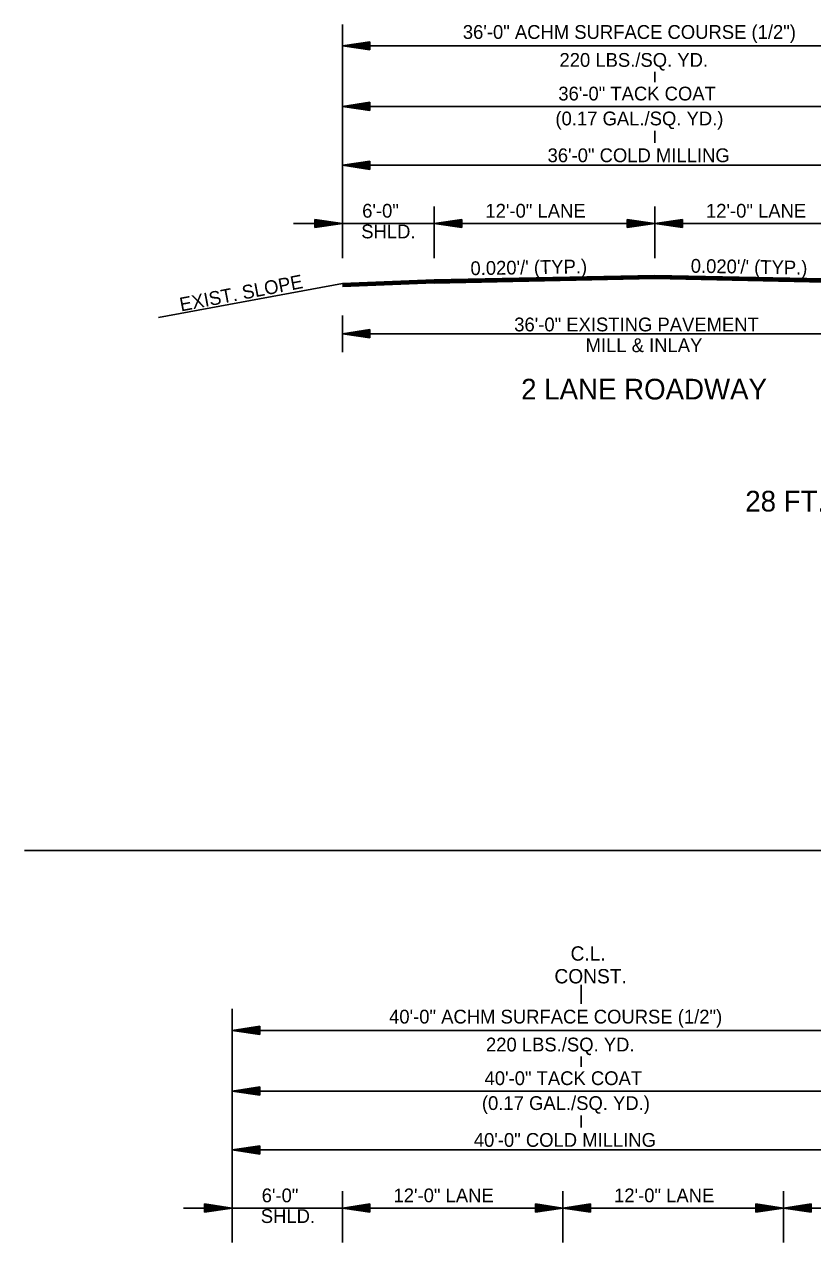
# Model space of a CAD drawing. Extents: x 549600 to 1930787, y -1955432 to 596640.
# Drawn here: x 551009 to 551438, y -1952647 to -1951984 of the extents above; entities that cross this region are included whole.
import ezdxf

# ---------------------------------------------------------------- set-up
doc = ezdxf.new("R2010")
doc.units = 0
doc.layers.add('R_Border', color=7, linetype='Continuous')
doc.layers.add('S_AREA_CALC', color=7, linetype='Continuous')

msp = doc.modelspace()

# ---------------------------------------------------------------- linework, layer by layer
at = {"layer": 'R_Border'}
msp.add_line((551008.97, -1952433.38), (552070.24, -1952433.38), dxfattribs=at)
at = {"layer": 'S_AREA_CALC'}
for p, q in [((551182.02, -1952111.3), (551182.02, -1951984.26)), ((551197.02, -1951993.68), (551182.02, -1951995.93)), ((551182.02, -1951995.93), (551522.02, -1951995.93)), ((551197.02, -1951998.18), (551182.02, -1951995.93)), ((551197.02, -1951994.06), (551184.52, -1951995.93)), ((551197.02, -1951997.81), (551184.52, -1951995.93)), ((551197.02, -1951994.44), (551187.1, -1951995.93)), ((551197.02, -1951997.43), (551187.1, -1951995.93)), ((551197.02, -1951994.82), (551189.6, -1951995.93)), ((551197.02, -1951997.05), (551189.6, -1951995.93)), ((551197.02, -1951995.2), (551192.14, -1951995.93)), ((551197.02, -1951996.66), (551192.14, -1951995.93)), ((551197.02, -1951995.58), (551194.65, -1951995.93)), ((551197.02, -1951996.29), (551194.65, -1951995.93)), ((551197.02, -1951998.18), (551197.02, -1951993.68)), ((551352.02, -1952015.68), (551352.02, -1952010.14)), ((551197.02, -1952026.65), (551182.02, -1952028.9)), ((551197.02, -1952031.15), (551182.02, -1952028.9)), ((551182.02, -1952028.9), (551522.02, -1952028.9)), ((551197.02, -1952027.02), (551184.52, -1952028.9)), ((551197.02, -1952030.77), (551184.52, -1952028.9)), ((551197.02, -1952027.41), (551187.1, -1952028.9)), ((551197.02, -1952030.39), (551187.1, -1952028.9)), ((551197.02, -1952027.78), (551189.6, -1952028.9)), ((551197.02, -1952030.02), (551189.6, -1952028.9)), ((551197.02, -1952028.16), (551192.14, -1952028.9)), ((551197.02, -1952029.63), (551192.14, -1952028.9)), ((551197.02, -1952028.55), (551194.65, -1952028.9)), ((551197.02, -1952029.25), (551194.65, -1952028.9)), ((551197.02, -1952031.15), (551197.02, -1952026.65)), ((551352.02, -1952048.64), (551352.02, -1952042.22)), ((551197.02, -1952058.62), (551182.02, -1952060.87)), ((551182.02, -1952060.87), (551522.02, -1952060.87)), ((551197.02, -1952063.12), (551182.02, -1952060.87)), ((551197.02, -1952059), (551184.52, -1952060.87)), ((551197.02, -1952062.75), (551184.52, -1952060.87)), ((551197.02, -1952059.38), (551187.1, -1952060.87)), ((551197.02, -1952062.37), (551187.1, -1952060.87)), ((551197.02, -1952059.76), (551189.6, -1952060.87)), ((551197.02, -1952061.99), (551189.6, -1952060.87)), ((551197.02, -1952060.14), (551192.14, -1952060.87)), ((551197.02, -1952061.6), (551192.14, -1952060.87)), ((551197.02, -1952060.52), (551194.65, -1952060.87)), ((551197.02, -1952061.23), (551194.65, -1952060.87)), ((551197.02, -1952063.12), (551197.02, -1952058.62)), ((551232.02, -1952111.3), (551232.02, -1952083.34)), ((551352.02, -1952111.3), (551352.02, -1952083.34)), ((551167.02, -1952090.28), (551182.02, -1952092.53)), ((551167.02, -1952090.28), (551167.02, -1952094.78)), ((551247.02, -1952090.28), (551232.02, -1952092.53)), ((551247.02, -1952090.28), (551247.02, -1952094.78)), ((551337.02, -1952090.28), (551352.02, -1952092.53)), ((551337.02, -1952090.28), (551337.02, -1952094.78)), ((551367.02, -1952090.28), (551352.02, -1952092.53)), ((551367.02, -1952090.28), (551367.02, -1952094.78)), ((551182.02, -1952092.53), (551155.5, -1952092.53)), ((551167.02, -1952090.66), (551179.51, -1952092.53)), ((551167.02, -1952091.04), (551176.93, -1952092.53)), ((551167.02, -1952091.42), (551174.44, -1952092.53)), ((551167.02, -1952091.81), (551171.89, -1952092.53)), ((551167.02, -1952092.18), (551169.39, -1952092.53)), ((551167.02, -1952094.78), (551182.02, -1952092.53)), ((551167.02, -1952093.27), (551171.89, -1952092.53)), ((551167.02, -1952094.03), (551176.93, -1952092.53)), ((551167.02, -1952094.41), (551179.51, -1952092.53)), ((551167.02, -1952093.65), (551174.44, -1952092.53)), ((551167.02, -1952092.89), (551169.39, -1952092.53)), ((551232.02, -1952092.53), (551182.02, -1952092.53)), ((551352.02, -1952092.53), (551232.02, -1952092.53)), ((551247.02, -1952094.78), (551232.02, -1952092.53)), ((551247.02, -1952090.66), (551234.52, -1952092.53)), ((551247.02, -1952094.41), (551234.52, -1952092.53)), ((551247.02, -1952091.04), (551237.1, -1952092.53)), ((551247.02, -1952094.03), (551237.1, -1952092.53)), ((551247.02, -1952091.42), (551239.6, -1952092.53)), ((551247.02, -1952093.65), (551239.6, -1952092.53)), ((551247.02, -1952091.81), (551242.14, -1952092.53)), ((551247.02, -1952093.27), (551242.14, -1952092.53)), ((551247.02, -1952092.18), (551244.65, -1952092.53)), ((551247.02, -1952092.89), (551244.65, -1952092.53)), ((551337.02, -1952090.66), (551349.51, -1952092.53)), ((551337.02, -1952091.04), (551346.93, -1952092.53)), ((551337.02, -1952091.42), (551344.44, -1952092.53)), ((551337.02, -1952091.81), (551341.89, -1952092.53)), ((551337.02, -1952092.18), (551339.39, -1952092.53)), ((551337.02, -1952094.78), (551352.02, -1952092.53)), ((551337.02, -1952093.27), (551341.89, -1952092.53)), ((551337.02, -1952094.03), (551346.93, -1952092.53)), ((551337.02, -1952094.41), (551349.51, -1952092.53)), ((551337.02, -1952093.65), (551344.44, -1952092.53)), ((551337.02, -1952092.89), (551339.39, -1952092.53)), ((551472.02, -1952092.53), (551352.02, -1952092.53)), ((551367.02, -1952094.78), (551352.02, -1952092.53)), ((551367.02, -1952090.66), (551354.52, -1952092.53)), ((551367.02, -1952094.41), (551354.52, -1952092.53)), ((551367.02, -1952091.04), (551357.1, -1952092.53)), ((551367.02, -1952094.03), (551357.1, -1952092.53)), ((551367.02, -1952091.42), (551359.6, -1952092.53)), ((551367.02, -1952093.65), (551359.6, -1952092.53)), ((551367.02, -1952091.81), (551362.14, -1952092.53)), ((551367.02, -1952093.27), (551362.14, -1952092.53)), ((551367.02, -1952092.18), (551364.65, -1952092.53)), ((551367.02, -1952092.89), (551364.65, -1952092.53)), ((551232.02, -1952123.24), (551182.02, -1952125.24)), ((551352.02, -1952120.84), (551232.02, -1952123.24)), ((551352.02, -1952121.14), (551232.02, -1952123.54)), ((551352.02, -1952121.44), (551232.02, -1952123.84)), ((551352.02, -1952121.74), (551232.02, -1952124.14)), ((551352.02, -1952122.04), (551232.02, -1952124.44)), ((551352.02, -1952122.34), (551232.02, -1952124.74)), ((551352.02, -1952122.51), (551232.02, -1952124.91)), ((551352.02, -1952120.84), (551472.02, -1952123.24)), ((551352.02, -1952121.14), (551472.02, -1952123.54)), ((551352.02, -1952121.44), (551472.02, -1952123.84)), ((551352.02, -1952121.74), (551472.02, -1952124.14)), ((551352.02, -1952122.04), (551472.02, -1952124.44)), ((551352.02, -1952122.34), (551472.02, -1952124.74)), ((551352.02, -1952122.51), (551472.02, -1952124.91)), ((551182.02, -1952125.24), (551081.95, -1952143.62)), ((551232.02, -1952123.54), (551182.02, -1952125.54)), ((551232.02, -1952123.84), (551182.02, -1952125.84)), ((551232.02, -1952124.14), (551182.02, -1952126.14)), ((551232.02, -1952124.44), (551182.02, -1952126.44)), ((551232.02, -1952124.74), (551182.02, -1952126.74)), ((551182.02, -1952142.5), (551182.02, -1952162.5)), ((551197.02, -1952150.25), (551182.02, -1952152.5)), ((551197.02, -1952154.75), (551182.02, -1952152.5)), ((551522.02, -1952152.5), (551182.02, -1952152.5)), ((551197.02, -1952150.63), (551184.52, -1952152.5)), ((551197.02, -1952154.38), (551184.52, -1952152.5)), ((551197.02, -1952151.01), (551187.1, -1952152.5)), ((551197.02, -1952153.99), (551187.1, -1952152.5)), ((551197.02, -1952151.38), (551189.6, -1952152.5)), ((551197.02, -1952153.62), (551189.6, -1952152.5)), ((551197.02, -1952151.77), (551192.14, -1952152.5)), ((551197.02, -1952153.24), (551192.14, -1952152.5)), ((551197.02, -1952152.15), (551194.65, -1952152.5)), ((551197.02, -1952152.85), (551194.65, -1952152.5)), ((551197.02, -1952150.25), (551197.02, -1952154.75)), ((551312.02, -1952516.8), (551312.02, -1952506.42)), ((551122.02, -1952646.64), (551122.02, -1952519.6)), ((551137.02, -1952529.03), (551122.02, -1952531.28)), ((551122.02, -1952531.28), (551522.02, -1952531.28)), ((551137.02, -1952533.53), (551122.02, -1952531.28)), ((551137.02, -1952529.4), (551124.52, -1952531.28)), ((551137.02, -1952533.15), (551124.52, -1952531.28)), ((551137.02, -1952529.78), (551127.1, -1952531.28)), ((551137.02, -1952532.77), (551127.1, -1952531.28)), ((551137.02, -1952530.16), (551129.6, -1952531.28)), ((551137.02, -1952532.39), (551129.6, -1952531.28)), ((551137.02, -1952530.54), (551132.14, -1952531.28)), ((551137.02, -1952532), (551132.14, -1952531.28)), ((551137.02, -1952530.92), (551134.65, -1952531.28)), ((551137.02, -1952531.63), (551134.65, -1952531.28)), ((551137.02, -1952533.53), (551137.02, -1952529.03)), ((551312.02, -1952551.02), (551312.02, -1952545.48)), ((551137.02, -1952561.99), (551122.02, -1952564.24)), ((551137.02, -1952566.49), (551122.02, -1952564.24)), ((551122.02, -1952564.24), (551522.02, -1952564.24)), ((551137.02, -1952562.37), (551124.52, -1952564.24)), ((551137.02, -1952566.12), (551124.52, -1952564.24)), ((551137.02, -1952562.75), (551127.1, -1952564.24)), ((551137.02, -1952565.73), (551127.1, -1952564.24)), ((551137.02, -1952563.12), (551129.6, -1952564.24)), ((551137.02, -1952565.36), (551129.6, -1952564.24)), ((551137.02, -1952563.51), (551132.14, -1952564.24)), ((551137.02, -1952564.97), (551132.14, -1952564.24)), ((551137.02, -1952563.89), (551134.65, -1952564.24)), ((551137.02, -1952564.59), (551134.65, -1952564.24)), ((551137.02, -1952566.49), (551137.02, -1952561.99)), ((551312.02, -1952583.98), (551312.02, -1952577.57)), ((551137.02, -1952593.97), (551122.02, -1952596.22)), ((551122.02, -1952596.22), (551522.02, -1952596.22)), ((551137.02, -1952598.47), (551122.02, -1952596.22)), ((551137.02, -1952594.34), (551124.52, -1952596.22)), ((551137.02, -1952598.09), (551124.52, -1952596.22)), ((551137.02, -1952594.72), (551127.1, -1952596.22)), ((551137.02, -1952597.71), (551127.1, -1952596.22)), ((551137.02, -1952595.1), (551129.6, -1952596.22)), ((551137.02, -1952597.33), (551129.6, -1952596.22)), ((551137.02, -1952595.48), (551132.14, -1952596.22)), ((551137.02, -1952596.94), (551132.14, -1952596.22)), ((551137.02, -1952595.86), (551134.65, -1952596.22)), ((551137.02, -1952596.57), (551134.65, -1952596.22)), ((551137.02, -1952598.47), (551137.02, -1952593.97)), ((551182.02, -1952646.64), (551182.02, -1952618.69)), ((551302.02, -1952646.64), (551302.02, -1952618.69)), ((551422.02, -1952646.64), (551422.02, -1952618.69)), ((551107.02, -1952625.63), (551122.02, -1952627.88)), ((551107.02, -1952625.63), (551107.02, -1952630.13)), ((551107.02, -1952626), (551119.51, -1952627.88)), ((551107.02, -1952626.38), (551116.93, -1952627.88)), ((551107.02, -1952626.76), (551114.44, -1952627.88)), ((551197.02, -1952625.63), (551182.02, -1952627.88)), ((551197.02, -1952626), (551184.52, -1952627.88)), ((551197.02, -1952626.38), (551187.1, -1952627.88)), ((551197.02, -1952626.76), (551189.6, -1952627.88)), ((551197.02, -1952625.63), (551197.02, -1952630.13)), ((551287.02, -1952625.63), (551302.02, -1952627.88)), ((551287.02, -1952625.63), (551287.02, -1952630.13)), ((551287.02, -1952626), (551299.51, -1952627.88)), ((551287.02, -1952626.38), (551296.93, -1952627.88)), ((551287.02, -1952626.76), (551294.44, -1952627.88)), ((551317.02, -1952625.63), (551302.02, -1952627.88)), ((551317.02, -1952626), (551304.52, -1952627.88)), ((551317.02, -1952626.38), (551307.1, -1952627.88)), ((551317.02, -1952626.76), (551309.6, -1952627.88)), ((551317.02, -1952625.63), (551317.02, -1952630.13)), ((551407.02, -1952625.63), (551422.02, -1952627.88)), ((551407.02, -1952625.63), (551407.02, -1952630.13)), ((551407.02, -1952626), (551419.51, -1952627.88)), ((551407.02, -1952626.38), (551416.93, -1952627.88)), ((551407.02, -1952626.76), (551414.44, -1952627.88)), ((551437.02, -1952625.63), (551422.02, -1952627.88)), ((551437.02, -1952626), (551424.52, -1952627.88)), ((551437.02, -1952626.38), (551427.1, -1952627.88)), ((551437.02, -1952626.76), (551429.6, -1952627.88)), ((551437.02, -1952625.63), (551437.02, -1952630.13)), ((551122.02, -1952627.88), (551095.5, -1952627.88)), ((551107.02, -1952627.15), (551111.89, -1952627.88)), ((551107.02, -1952627.52), (551109.39, -1952627.88)), ((551107.02, -1952630.13), (551122.02, -1952627.88)), ((551107.02, -1952628.61), (551111.89, -1952627.88)), ((551107.02, -1952629.37), (551116.93, -1952627.88)), ((551107.02, -1952629.75), (551119.51, -1952627.88)), ((551107.02, -1952628.99), (551114.44, -1952627.88)), ((551107.02, -1952628.23), (551109.39, -1952627.88)), ((551182.02, -1952627.88), (551122.02, -1952627.88)), ((551302.02, -1952627.88), (551182.02, -1952627.88)), ((551197.02, -1952630.13), (551182.02, -1952627.88)), ((551197.02, -1952629.75), (551184.52, -1952627.88)), ((551197.02, -1952629.37), (551187.1, -1952627.88)), ((551197.02, -1952628.99), (551189.6, -1952627.88)), ((551197.02, -1952627.15), (551192.14, -1952627.88)), ((551197.02, -1952628.61), (551192.14, -1952627.88)), ((551197.02, -1952627.52), (551194.65, -1952627.88)), ((551197.02, -1952628.23), (551194.65, -1952627.88)), ((551287.02, -1952627.15), (551291.89, -1952627.88)), ((551287.02, -1952627.52), (551289.39, -1952627.88)), ((551287.02, -1952630.13), (551302.02, -1952627.88)), ((551287.02, -1952628.61), (551291.89, -1952627.88)), ((551287.02, -1952629.37), (551296.93, -1952627.88)), ((551287.02, -1952629.75), (551299.51, -1952627.88)), ((551287.02, -1952628.99), (551294.44, -1952627.88)), ((551287.02, -1952628.23), (551289.39, -1952627.88)), ((551422.02, -1952627.88), (551302.02, -1952627.88)), ((551317.02, -1952630.13), (551302.02, -1952627.88)), ((551317.02, -1952629.75), (551304.52, -1952627.88)), ((551317.02, -1952629.37), (551307.1, -1952627.88)), ((551317.02, -1952628.99), (551309.6, -1952627.88)), ((551317.02, -1952627.15), (551312.14, -1952627.88)), ((551317.02, -1952628.61), (551312.14, -1952627.88)), ((551317.02, -1952627.52), (551314.65, -1952627.88)), ((551317.02, -1952628.23), (551314.65, -1952627.88)), ((551407.02, -1952627.15), (551411.89, -1952627.88)), ((551407.02, -1952627.52), (551409.39, -1952627.88)), ((551407.02, -1952630.13), (551422.02, -1952627.88)), ((551407.02, -1952628.61), (551411.89, -1952627.88)), ((551407.02, -1952629.37), (551416.93, -1952627.88)), ((551407.02, -1952629.75), (551419.51, -1952627.88)), ((551407.02, -1952628.99), (551414.44, -1952627.88)), ((551407.02, -1952628.23), (551409.39, -1952627.88)), ((551422.02, -1952627.88), (551522.02, -1952627.88)), ((551437.02, -1952630.13), (551422.02, -1952627.88)), ((551437.02, -1952629.75), (551424.52, -1952627.88)), ((551437.02, -1952629.37), (551427.1, -1952627.88)), ((551437.02, -1952628.99), (551429.6, -1952627.88)), ((551437.02, -1952627.15), (551432.14, -1952627.88)), ((551437.02, -1952628.61), (551432.14, -1952627.88)), ((551437.02, -1952627.52), (551434.65, -1952627.88)), ((551437.02, -1952628.23), (551434.65, -1952627.88))]:
    msp.add_line(p, q, dxfattribs=at)

# ---------------------------------------------------------------- texts
at = {"layer": 'R_Border'}
msp.add_text('28 FT. CLEAR ROADWAY BRIDGE - HYDRODEMOLITION', height=11.25, dxfattribs=at).set_placement((551401.23, -1952249.12))
at = {"layer": 'S_AREA_CALC'}
for s, height, p in [('36\'-0" ACHM SURFACE COURSE (1/2")', 7.5, (551247.55, -1951992.16)), ('220 LBS./SQ. YD. ', 7.5, (551300.14, -1952007.35)), ('36\'-0" TACK COAT', 7.5, (551299.49, -1952025.64)), ('(0.17 GAL./SQ. YD.)', 7.5, (551297.93, -1952039.18)), ('36\'-0" COLD MILLING ', 7.5, (551293.64, -1952059.2)), ('6\'-0"', 7.5, (551192.78, -1952089.36)), ('12\'-0" LANE', 7.5, (551259.84, -1952089.36)), ('12\'-0" LANE', 7.5, (551379.84, -1952089.36)), ('SHLD.', 7.5, (551192.28, -1952100.61)), ('36\'-0" EXISTING PAVEMENT', 7.5, (551275.51, -1952151.18)), ('MILL & INLAY', 7.5, (551314.34, -1952162.46)), ('2 LANE ROADWAY', 11.25, (551279.29, -1952188.22)), ('C.L.', 7.8, (551306.17, -1952493.33)), ('CONST.', 7.8, (551297.39, -1952505.69)), ('40\'-0" ACHM SURFACE COURSE (1/2")', 7.5, (551207.43, -1952527.51)), ('220 LBS./SQ. YD. ', 7.5, (551260.14, -1952542.69)), ('40\'-0" TACK COAT', 7.5, (551259.37, -1952560.98)), ('(0.17 GAL./SQ. YD.)', 7.5, (551257.93, -1952574.52)), ('40\'-0" COLD MILLING ', 7.5, (551253.52, -1952594.55)), ('6\'-0"', 7.5, (551138.11, -1952624.71)), ('12\'-0" LANE', 7.5, (551209.84, -1952624.71)), ('12\'-0" LANE', 7.5, (551329.84, -1952624.71)), ('SHLD.', 7.5, (551137.61, -1952635.96))]:
    msp.add_text(s, height=height, dxfattribs=at).set_placement(p)
for s, rotation, p in [("0.020'/' (TYP.)", 0.97192, (551251.76, -1952120.64)), ("0.020'/' (TYP.)", 359.02808, (551371.5, -1952119.27)), ('EXIST. SLOPE', 10.88286, (551094.23, -1952140.4))]:
    msp.add_text(s, height=7.5, rotation=rotation, dxfattribs=at).set_placement(p)

doc.saveas('drawing.dxf')
